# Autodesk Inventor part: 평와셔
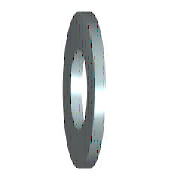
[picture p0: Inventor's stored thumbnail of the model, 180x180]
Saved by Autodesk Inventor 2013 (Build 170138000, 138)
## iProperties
IsCustomPart: 1
Created: 2012-02
Part Number: 평와셔
Material: 강철
Description: 평면 와셔 - 초대형 시리즈 - 제품 등급 C
Document SubType Name: Modeling
Standard: ISO 7094
Designer: mduedu
Standard Revision: Second edition 2000-06-01
Standards Organization: ISO
Language: ko-KR
Size Designation: ST 5 - 100 HV
Categories: <MemberInstance><Categories><Category DisplayName="조임쇠" InternalName="e4da775c-781d-43d5-af7c-5136215cf5a6" Mnemonic="FSTN"><Category DisplayName="와셔" InternalN
Density: 7.85 g/cm^3
Author: mduedu
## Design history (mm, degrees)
sketch "스케치"
  geometry: C1 r 9 at (0, 0); C2 r 2.75 at (0, 0); 1 further point
  constraints: 2 centre point, 2 coincident
  dimensions: "d0" = 5.5 diameter of C2 (= SD1); "d1" = 18 diameter of C1 (= SD2)
extrude "본체" new body sketch "스케치" distance "d2" = 2 (= SD); taper "d3" = 0 deg
workaxis "Work Axis1"
workplane "Work Plane1"
body "Solid1"
other parameters: "SD1" = 5.5 [user parameter; used in 1 equation term], "SD2" = 18 [user parameter; used in 1 equation term], "SD" = 2 [user parameter; used in 1 equation term], "d4" = 0, "d5" = 0, "d6" = 0, "d7" = 0, "NND" = 5 [user parameter]
